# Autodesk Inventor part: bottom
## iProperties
Author: Elise Moss
Created: 2001-09
Part Number: bottom
Document SubType Name: Modeling
Designer: Elise Moss
Control State: 0
Master: False
Checked Out: False
PropertySet Name: Design Tracking Control
Shininess: 64.0
Angle Display Precision: 2
Document Length Units: 11272
Document Angle Units: 11286
Document Time Units: 11279
Document Mass Units: 11290
Document Length Units Precision: 3
Document Angle Units Precision: 2
Compacted: False
PropertySet Name: _Private Model Information
Density: 0.0
Volumn: 0.0
Area: 0.0
PropertySet Name: Model Information
